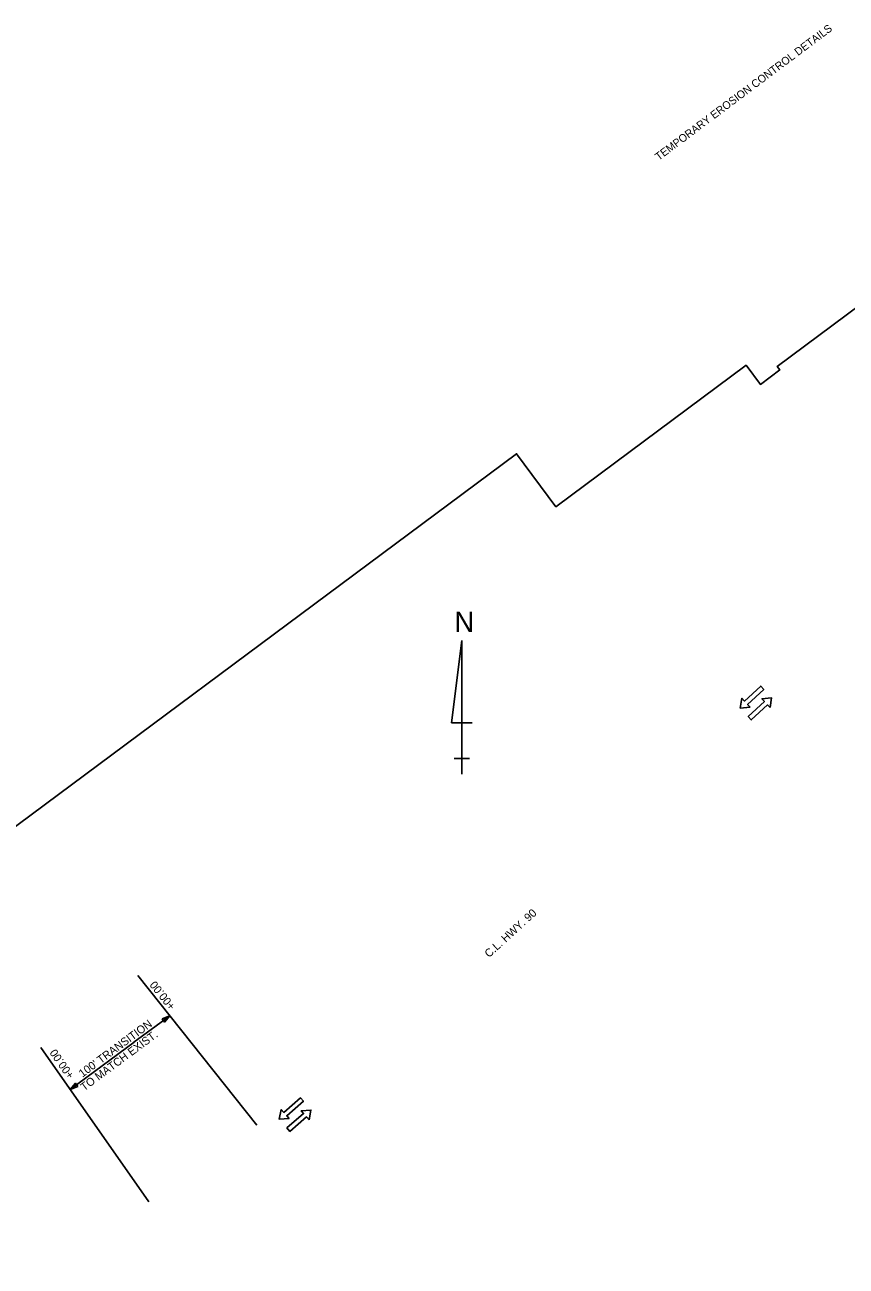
# Model space of a CAD drawing. Extents: x 1571137 to 1573037, y 731597 to 733459.
# Drawn here: x 1571718 to 1572334, y 732528 to 733459 of the extents above; entities that cross this region are included whole.
import ezdxf

# ---------------------------------------------------------------- set-up
doc = ezdxf.new("R2010")
doc.units = 0
for name, color, linetype in [('R_Annotation', 7, 'Continuous'), ('R_Draft', 7, 'Continuous'), ('R_MOT', 7, 'Continuous'), ('R_Proposed Road_Lane', 7, 'Continuous'), ('S_EXIST_ROW', 7, 'Continuous'), ('S_MSC_PT_SYM', 7, 'Continuous')]:
    doc.layers.add(name, color=color, linetype=linetype)

msp = doc.modelspace()

# ---------------------------------------------------------------- linework, layer by layer
at = {"layer": 'R_Draft'}
for p, q in [((1571802.99, 732746), (1571892.26, 732633.68)), ((1571800.14, 732695.92), (1571826.93, 732715.8)), ((1571730.33, 732692.08), (1571811.32, 732576.33)), ((1571800.16, 732695.89), (1571752.44, 732660.48))]:
    msp.add_line(p, q, dxfattribs=at)
for points in [[(1571821.22, 732713.43), (1571826.93, 732715.8), (1571823, 732711.02)], [(1571758.15, 732662.85), (1571752.44, 732660.48), (1571756.37, 732665.26)]]:
    msp.add_lwpolyline(points, close=True, dxfattribs=at)
at = {"layer": 'R_MOT'}
for points in [[(1572261.78, 732947.23), (1572254.43, 732946.57), (1572255.66, 732953.84), (1572257.57, 732951.77), (1572269.72, 732963.02), (1572272.01, 732960.54), (1572259.87, 732949.3)], [(1572276.72, 732946.86), (1572277.95, 732954.13), (1572270.6, 732953.46), (1572272.51, 732951.4), (1572260.37, 732940.16), (1572262.66, 732937.68), (1572274.81, 732948.92)], [(1571916.41, 732638.69), (1571909.05, 732638.25), (1571910.5, 732645.48), (1571912.35, 732643.36), (1571924.83, 732654.22), (1571927.05, 732651.68), (1571914.56, 732640.81)], [(1571931.33, 732637.86), (1571932.78, 732645.09), (1571925.42, 732644.65), (1571927.27, 732642.52), (1571914.78, 732631.66), (1571917, 732629.11), (1571929.48, 732639.98)]]:
    msp.add_lwpolyline(points, close=True, dxfattribs=at)
at = {"layer": 'R_Proposed Road_Lane'}
for p, q in [((1572045.85, 732997.08), (1572038.16, 732935.54)), ((1572045.85, 732897.08), (1572045.85, 732997.08)), ((1572045.85, 732997.08), (1572045.85, 732920.15)), ((1572038.16, 732935.54), (1572053.55, 732935.54)), ((1572045.85, 732897.08), (1572045.85, 732920.15)), ((1572045.85, 732908.62), (1572040.08, 732908.62)), ((1572040.08, 732908.62), (1572051.62, 732908.62)), ((1572045.85, 732897.08), (1572045.85, 732908.62))]:
    msp.add_line(p, q, dxfattribs=at)
at = {"layer": 'S_MSC_PT_SYM'}
msp.add_lwpolyline([(1572536.74, 733221.56), (1573036.71, 732549.76), (1571756.88, 731597.29), (1571136.98, 732430.24), (1572086.85, 733137.16), (1572116.34, 733097.53), (1572258.81, 733203.56), (1572269.47, 733189.25), (1572284.07, 733200.11), (1572282.13, 733202.72), (1572344.44, 733249.09)], dxfattribs=at)

# ---------------------------------------------------------------- texts
at = {"layer": 'R_Annotation'}
for s, rotation, p in [('C.L. HWY. 90', 42.35253, (1572066.16, 732759.04)), ('+00.00', 128.47724, (1571831.55, 732723.11)), ("100' TRANSITION", 36.57639, (1571761.51, 732669.32)), ('TO MATCH EXIST.', 36.57639, (1571762.83, 732659.09)), ('+00.00', 124.97725, (1571755.67, 732671.18))]:
    msp.add_text(s, height=6, rotation=rotation, dxfattribs=at).set_placement(p)
at = {"layer": 'R_Proposed Road_Lane'}
msp.add_text('N', height=15.38, dxfattribs=at).set_placement((1572040.22, 733003.49))
at = {"layer": 'S_EXIST_ROW'}
msp.add_text('TEMPORARY EROSION CONTROL DETAILS', height=5.862, rotation=36.96355, dxfattribs=at).set_placement((1572193.37, 733356.75))

doc.saveas('drawing.dxf')
